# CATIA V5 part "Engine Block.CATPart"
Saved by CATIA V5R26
Part number: Part1
Bounding box of the stored display mesh (mm): x 0 to 150, y 0 to 40, z 0 to 43
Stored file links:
  D:\_Deepak\CATIA\New Chapter\C19 FEA\Tutorial\TUT04\Engine Block.CATPart
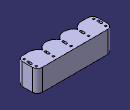
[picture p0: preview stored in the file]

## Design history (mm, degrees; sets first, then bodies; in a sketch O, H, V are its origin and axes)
Body1 (main body)
  Sketch1 on xy-plane, origin (0, 0, 0), H (1, 0, 0), V (0, 1, 0)
    line L1 (10, 0) -> (140, 0)
    line L2 (150, 10) -> (150, 30)
    line L3 (140, 40) -> (10, 40)
    line L4 (0, 30) -> (0, 10)
    arc A1 centre (10, 10) radius 10 from (10, 0) to (0, 10) cw
    arc A2 centre (140, 10) radius 10 from (140, 0) to (150, 10) ccw
    arc A3 centre (140, 30) radius 10 from (150, 30) to (140, 40) ccw
    arc A4 centre (10, 30) radius 10 from (10, 40) to (0, 30) ccw
    radius A1 = 10
    radius A2 = 10
    radius A3 = 10
    radius A4 = 10
    distance L2 L4 = 150
    distance L3 L1 = 40
    horizontal: L1 H, L3 H
    vertical: L2 V, L4 V
    coincidence: L1 O, L4 O
    tangency: A1 L1, A1 L4, A2 L1, A2 L2, A3 L2, A3 L3, A4 L3, A4 L4
  Pad1: profile Sketch1, direction (0, 0, 1), length 43
  Sketch2 on xy-plane, origin (0, 0, 0), H (1, 0, 0), V (0, 1, 0)
    circle A1 centre (22.5, 20) radius 12.5
    point P1 (22.5, 20)
    point P2 (57.5, 20)
    circle A2 centre (57.5, 20) radius 12.5
    point P3 (92.5, 20)
    circle A3 centre (92.5, 20) radius 12.5
    point P4 (127.5, 20)
    circle A4 centre (127.5, 20) radius 12.5
    reference projected line E1 (140, 40) -> (10, 40) from edge [face of Pad1 from Sketch1.L3 | end face of Pad1]
    construction line L1 (22.5, 20) -> (160.4972, 20)
    axis line L2 (75, 83.7885) -> (75, -11.6317)
    reference projected line E2 (150, 10) -> (150, 30) from edge [face of Pad1 from Sketch1.L2 | end face of Pad1]
    reference projected line E3 (0, 30) -> (0, 10) from edge [face of Pad1 from Sketch1.L4 | end face of Pad1]
    radius A2 = 12.5
    radius A3 = 12.5
    radius A4 = 12.5
    distance P1 E1 = 20
    distance P1 P2 = 35
    distance P2 P3 = 35
    distance P3 P4 = 35
    horizontal: L1 H
    coincidence: L1 P2, L1 P3, P4 L1
    symmetry: E2 E3 L2, A4 A1 L2
  Pocket1: profile Sketch2, direction (0, 0, 1), length 40
  Sketch3 on start face of Pad1, origin (0, 0, 0), H (1, 0, 0), V (0, -1, 0)
    arc A1 centre (22.5, -20) radius 20 from (40, -10.3175) to (22.4999, 0) ccw
    arc A2 centre (57.5, -20) radius 20 from (57.5, 0) to (40, -10.3175) ccw
    reference projected circle E1 centre (57.5, -20) radius 12.5 from edge [face of Pocket1 from Sketch2.A2 | start face of Pad1]
    reference projected circle E2 centre (22.5, -20) radius 12.5 from edge [face of Pocket1 from Sketch2.A1 | start face of Pad1]
    line L1 (22.4999, 0) -> (57.5, 0)
    radius A1 = 20
    radius A2 = 20
    concentricity: A2 E1, E2 A1
    fix: L1
  Pocket2: profile Sketch3, direction (0, 0, 1), through (limit type 6)
  RectPattern1: of Pocket2, direction 1 instances 3, spacing 35, along edge [start face of Pad1 | face of Pad1 from Sketch1.L1]
  Sketch4 on start face of Pad1, origin (0, 0, 0), H (1, 0, 0), V (0, -1, 0)
    circle A1 centre (6, -32) radius 2
    point P2 (40, -32)
    circle A2 centre (40, -32) radius 2
    point P3 (75, -32)
    circle A3 centre (75, -32) radius 2
    point P4 (110, -32)
    circle A4 centre (110, -32) radius 2
    circle A5 centre (144, -32) radius 2
    construction line L1 (6, -32) -> (144, -32)
    construction line L2 (40, 4.6658) -> (40, -59.1562)
    reference projected point E1 (40, -10.3175) from vertex [start face of Pad1 | face of Pocket2 from Sketch3.A2 | face of Pocket2 from Sketch3.A1]
    construction line L3 (110, 9.612) -> (110, -55.4864)
    construction line L4 (75, 52.0631) -> (75, -75.4722)
    reference projected line E2 (0, -30) -> (0, -10) from edge [start face of Pad1 | face of Pad1 from Sketch1.L4]
    reference projected line E3 (150, -10) -> (150, -30) from edge [start face of Pad1 | face of Pad1 from Sketch1.L2]
    reference projected point E4 (110, -10.3175) from vertex [face of RectPattern1 | face of RectPattern1 | start face of Pad1]
    axis line L5 (-9.2648, -20) -> (155.2665, -20)
    reference projected line E5 (10, 0) -> (140, 0) from edge [start face of Pad1 | face of Pad1 from Sketch1.L1]
    reference projected line E6 (140, -40) -> (10, -40) from edge [start face of Pad1 | face of Pad1 from Sketch1.L3]
    circle A6 centre (6, -8) radius 2
    circle A7 centre (144, -8) radius 2
    radius A1 = 2
    radius A2 = 2
    radius A3 = 2
    radius A4 = 2
    horizontal: L1 H, L5 H
    coincidence: P4 L1, P3 L1, P2 L1, L2 E1, P2 L2, P4 L3, P3 L4, L3 E4
    vertical: L2 V, L3 V, L4 V
    symmetry: E2 E3 L4, A1 A5 L4, E5 E6 L5, A1 A6 L5, A5 A7 L5
    fix: A1
  Pocket3: profile Sketch4, direction (0, 0, 1), through (limit type 6)
  Sketch5 on start face of Pad1, origin (0, 0, 0), H (1, 0, 0), V (0, -1, 0)
    construction line L1 (40, -22.3175) -> (40, -16.3175)
    point P2 (40, -16.3175)
    line L2 (38, -22.3175) -> (38, -16.3175)
    line L3 (42, -16.3175) -> (42, -22.3175)
    arc A1 centre (40, -16.3175) radius 2 from (38, -16.3175) to (42, -16.3175) cw
    arc A2 centre (40, -22.3175) radius 2 from (42, -22.3175) to (38, -22.3175) cw
    point P3 (38, -22.3175)
    point P4 (38, -16.3175)
    point P5 (42, -16.3175)
    point P6 (42, -22.3175)
    reference projected point E1 (40, -10.3175) from vertex [start face of Pad1 | face of Pocket2 from Sketch3.A2 | face of Pocket2 from Sketch3.A1]
    reference projected point E2 (40, -10.3175) from vertex [start face of Pad1 | face of Pocket2 from Sketch3.A2 | face of Pocket2 from Sketch3.A1]
    point P7 (75, -16.3175)
    point P8 (75, -22.3175)
    construction line L4 (75, -22.3175) -> (75, -16.3175)
    point P9 (73, -22.3175)
    point P10 (73, -16.3175)
    point P11 (77, -16.3175)
    point P12 (77, -22.3175)
    line L5 (73, -22.3175) -> (73, -16.3175)
    line L6 (77, -16.3175) -> (77, -22.3175)
    arc A3 centre (75, -16.3175) radius 2 from (73, -16.3175) to (77, -16.3175) cw
    arc A4 centre (75, -22.3175) radius 2 from (77, -22.3175) to (73, -22.3175) cw
    reference projected point E3 (75, -10.3175) from vertex [face of RectPattern1 | face of RectPattern1 | start face of Pad1]
    construction line L7 (110, -22.3175) -> (110, -16.3175)
    point P15 (112, -22.3175)
    point P16 (112, -16.3175)
    point P17 (108, -16.3175)
    point P18 (108, -22.3175)
    line L8 (112, -22.3175) -> (112, -16.3175)
    line L9 (108, -16.3175) -> (108, -22.3175)
    arc A5 centre (110, -16.3175) radius 2 from (112, -16.3175) to (108, -16.3175) ccw
    arc A6 centre (110, -22.3175) radius 2 from (108, -22.3175) to (112, -22.3175) ccw
    reference projected point E4 (75, -10.3175) from vertex [face of RectPattern1 | face of RectPattern1 | start face of Pad1]
    axis line L10 (40, -22.3175) -> (110, -22.3175)
    construction line L11 (5, -22.3175) -> (5, -16.3175)
    point P21 (7, -22.3175)
    point P22 (7, -16.3175)
    point P23 (3, -16.3175)
    point P24 (3, -22.3175)
    line L12 (7, -22.3175) -> (7, -16.3175)
    line L13 (3, -16.3175) -> (3, -22.3175)
    arc A7 centre (5, -16.3175) radius 2 from (7, -16.3175) to (3, -16.3175) ccw
    arc A8 centre (5, -22.3175) radius 2 from (3, -22.3175) to (7, -22.3175) ccw
    construction line L14 (145, -22.3175) -> (145, -16.3175)
    point P27 (147, -22.3175)
    point P28 (147, -16.3175)
    point P29 (143, -16.3175)
    point P30 (143, -22.3175)
    line L15 (147, -22.3175) -> (147, -16.3175)
    line L16 (143, -16.3175) -> (143, -22.3175)
    arc A9 centre (145, -16.3175) radius 2 from (147, -16.3175) to (143, -16.3175) ccw
    arc A10 centre (145, -22.3175) radius 2 from (143, -22.3175) to (147, -22.3175) ccw
    distance L1 L2 = 2
    length L1 = 6
    distance P2 E2 = 6
    distance P7 E4 = 6
    radius A3 = 2
    distance L5 L6 = 4
    vertical: L1 V
    tangency: A1 L2, A2 L2, A1 L3, A2 L3
    coincidence: L1 E1, L4 E3, L10 P8
    symmetry: L1 L7 L4, P3 P15 L4, P4 P16 L4, P5 P17 L4, P6 P18 L4, L2 L8 L4, L3 L9 L4, A1 A5 L4, A2 A6 L4, L4 L11 L1, P9 P21 L1, P10 P22 L1, P11 P23 L1, P12 P24 L1, L5 L12 L1, L6 L13 L1, A3 A7 L1, A4 A8 L1, L4 L14 L7, P9 P27 L7, P10 P28 L7, P11 P29 L7, P12 P30 L7, L5 L15 L7, L6 L16 L7, A3 A9 L7, A4 A10 L7
    horizontal: L10 H
  Pocket4: profile Sketch5, direction (0, 0, 1), through (limit type 6)
  Sketch6 on start face of Pad1, origin (0, 0, 0), H (1, 0, 0), V (0, -1, 0)
    construction line L1 (-2.1155, -20) -> (152.3983, -20)
    reference projected line E1 (10, 0) -> (140, 0) from edge [start face of Pad1 | face of Pad1 from Sketch1.L1]
    reference projected line E2 (140, -40) -> (10, -40) from edge [start face of Pad1 | face of Pad1 from Sketch1.L3]
    circle A1 centre (22, -4) radius 1.5
    point P3 (22, -4)
    circle A2 centre (22, -36) radius 1.5
    construction line L2 (40, 18.8361) -> (40, -51.6721)
    reference projected point E3 (40, -10.3175) from vertex [start face of Pad1 | face of RectPattern1 | face of Pocket2 from Sketch3.A1]
    circle A3 centre (58, -4) radius 1.5
    axis line L3 (75, 12.6867) -> (75, -50.2038)
    reference projected point E4 (75, -10.3175) from vertex [face of RectPattern1 | face of RectPattern1 | start face of Pad1]
    circle A4 centre (58, -36) radius 1.5
    circle A5 centre (128, -4) radius 1.5
    circle A6 centre (128, -36) radius 1.5
    circle A7 centre (92, -36) radius 1.5
    circle A8 centre (92, -4) radius 1.5
    radius A1 = 1.5
    distance P3 V = 22
    distance P3 L1 = 16
    horizontal: L1 H
    symmetry: E1 E2 L1, A1 A2 L1, A1 A3 L2, A2 A4 L2, A1 A5 L3, A2 A6 L3, A4 A7 L3, A3 A8 L3
    vertical: L2 V, L3 V
    coincidence: E3 L2, L3 E4
  Pocket5: profile Sketch6, direction (0, 0, 1), length 10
